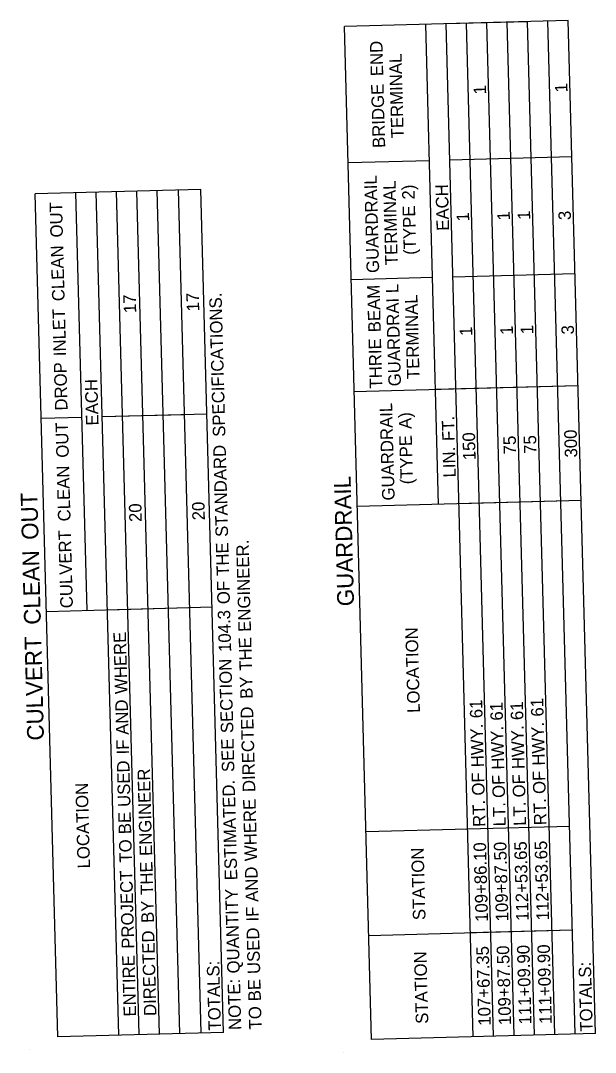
# Model space of a CAD drawing. Extents: x 1930093 to 1931323, y 596452 to 607874.
# Drawn here: x 1930956 to 1931231.4, y 599182.3 to 599676.8 of the extents above; entities that cross this region are included whole.
import ezdxf

# ---------------------------------------------------------------- set-up
doc = ezdxf.new("R2010")
doc.units = 0
doc.layers.add('Default', color=7, linetype='Continuous')
doc.layers.add('R_Border', color=7, linetype='Continuous')

msp = doc.modelspace()

# ---------------------------------------------------------------- linework, layer by layer
at = {"layer": 'Default'}
for p, q in [((1931218.38, 599676.81), (1931111.17, 599673.93)), ((1931198.89, 599676.28), (1931159.9, 599675.24)), ((1931172.93, 599189.86), (1931159.9, 599675.24)), ((1931182.68, 599190.12), (1931169.65, 599675.5)), ((1931192.43, 599190.39), (1931179.4, 599675.76)), ((1931202.17, 599190.65), (1931189.14, 599676.02)), ((1931211.92, 599190.91), (1931198.89, 599676.28)), ((1931221.67, 599191.17), (1931208.64, 599676.55)), ((1931231.41, 599191.43), (1931218.38, 599676.81)), ((1931124.2, 599188.55), (1931111.17, 599673.93)), ((1931156.33, 599444.96), (1931150.16, 599674.98)), ((1931220.14, 599611.51), (1931161.66, 599609.94)), ((1931220.14, 599611.51), (1931161.66, 599609.94)), ((1931151.91, 599609.67), (1931112.92, 599608.63)), ((1931042.44, 599595.93), (1930963, 599593.8)), ((1931042.44, 599595.93), (1930963, 599593.8)), ((1930973.85, 599189.81), (1930963, 599593.8)), ((1930987.87, 599394.03), (1930982.5, 599594.32)), ((1931003.09, 599190.59), (1930992.24, 599594.58)), ((1931012.83, 599190.85), (1931001.99, 599594.84)), ((1931022.58, 599191.11), (1931011.74, 599595.11)), ((1931032.33, 599191.38), (1931021.48, 599595.37)), ((1931042.56, 599191.65), (1931031.72, 599595.64)), ((1931042.56, 599191.65), (1931031.72, 599595.64)), ((1931053.28, 599191.94), (1931042.44, 599595.93)), ((1931153.41, 599553.63), (1931114.43, 599552.59)), ((1931221.64, 599555.46), (1931163.16, 599553.89)), ((1931221.64, 599555.46), (1931163.16, 599553.89)), ((1931223.08, 599501.86), (1931115.87, 599498.98)), ((1931223.08, 599501.86), (1931154.85, 599500.03)), ((1931045.33, 599488.23), (1930995.13, 599486.88)), ((1931034.61, 599487.94), (1930995.13, 599486.88)), ((1930985.39, 599486.62), (1930965.89, 599486.1)), ((1931224.56, 599446.79), (1931117.35, 599443.91)), ((1931224.56, 599446.79), (1931166.08, 599445.22)), ((1931047.81, 599395.64), (1930968.38, 599393.51)), ((1931047.81, 599395.64), (1930997.62, 599394.29)), ((1931219, 599290.58), (1931121.53, 599287.97)), ((1931219, 599290.58), (1931170.26, 599289.28)), ((1931220.33, 599240.88), (1931122.87, 599238.26)), ((1931220.33, 599240.88), (1931171.6, 599239.57)), ((1931053.28, 599191.94), (1930973.85, 599189.81)), ((1931053.28, 599191.94), (1930973.85, 599189.81)), ((1931231.41, 599191.43), (1931124.2, 599188.55)), ((1931231.41, 599191.43), (1931124.2, 599188.55))]:
    msp.add_line(p, q, dxfattribs=at)
at = {"layer": 'R_Border'}
for p, q in [((1930960.36, 599183.59), (1930960.36, 599183.59)), ((1931110.71, 599182.34), (1931110.71, 599182.34))]:
    msp.add_line(p, q, dxfattribs=at)

# ---------------------------------------------------------------- texts
at = {"layer": 'Default'}
for s, height, p in [(' END', 6, (1931129.87, 599648.05)), ('TERMINAL', 6, (1931139.62, 599620.48)), ('BRIDGE', 6, (1931130.74, 599615.87)), ('1', 6, (1931179.12, 599641.52)), ('1', 6, (1931218.1, 599642.47)), ('GUARDRAIL', 6, (1931127.84, 599555.95)), ('TERMINAL', 6, (1931136.75, 599559.69)), (' 2)', 6, (1931144.96, 599588.92)), ('EACH', 6, (1931161.36, 599576.18)), (' OUT', 6, (1930976.38, 599570.73)), ('(TYPE', 6, (1931145.62, 599564.65)), ('1', 6, (1931171, 599580.59)), ('1', 6, (1931190.49, 599581.11)), ('1', 6, (1931200.24, 599581.37)), ('3', 6, (1931219.75, 599581.3)), (' CLEAN', 6, (1930977.2, 599540.2)), (' BEAM', 6, (1931128.67, 599525.31)), ('L', 6, (1931137.11, 599546.26)), ('17', 6, (1931011.43, 599536.74)), ('17', 6, (1931041.64, 599537.54)), (' SPECIFICATIONS.', 6, (1931054.23, 599475.21)), ('GUARDRAI', 6, (1931138.3, 599501.64)), ('TERMINAL', 6, (1931147.21, 599505.11)), (' INLET', 6, (1930977.9, 599513.84)), ('1', 6, (1931172.47, 599525.76)), ('1', 6, (1931191.96, 599526.28)), ('1', 6, (1931201.71, 599526.55)), ('3', 6, (1931221.22, 599526.48)), ('THRIE', 6, (1931129.33, 599500.58)), ('DROP', 6, (1930978.54, 599490.01)), ('EACH', 6, (1930993.37, 599482.83)), ('GUARDRAIL', 6, (1931135.27, 599446.91)), (' A)', 6, (1931143.42, 599478.94)), (' OUT', 6, (1930979.21, 599465.19)), (' FT.', 6, (1931164.13, 599473.19)), ('(TYPE', 6, (1931144.07, 599454.67)), ('150', 6, (1931174.07, 599466.2)), ('75', 6, (1931193.5, 599469.02)), ('75', 6, (1931203.25, 599469.28)), ('300', 6, (1931222.8, 599467.51)), (' STANDARD', 6, (1931055.52, 599427.22)), ('LIN.', 6, (1931164.54, 599457.94)), (' CLEAN', 6, (1930980.03, 599434.66)), ('GUARDRAIL', 8, (1931115.8, 599396.26)), (' OUT', 8, (1930964.7, 599425.12)), ('20', 6, (1931014.11, 599436.6)), ('20', 6, (1931044.33, 599437.42)), ('CULVERT', 6, (1930981.09, 599395.26)), (' THE', 6, (1931056.02, 599408.58)), (' ENGINEER.', 6, (1931066.49, 599381.74)), (' CLEAN', 8, (1930965.8, 599384.42)), (' OF', 6, (1931056.38, 599395)), (' 104.3', 6, (1931057, 599372.09)), (' WHERE', 6, (1931007.31, 599351.94)), ('LOCATION', 6, (1931147.38, 599345.13)), ('CULVERT', 8, (1930967.21, 599331.88)), (' THE', 6, (1931066.99, 599363.1)), (' SECTION', 6, (1931058.04, 599333.2)), (' BY', 6, (1931067.35, 599349.65)), (' AND', 6, (1931007.83, 599332.36)), (' 61', 6, (1931177.45, 599340.31)), (' 61', 6, (1931187.23, 599339.17)), (' 61', 6, (1931196.98, 599339.43)), (' 61', 6, (1931206.69, 599341.09)), (' DIRECTED', 6, (1931068.55, 599304.94)), (' HWY.', 6, (1931178.08, 599316.83)), (' HWY.', 6, (1931207.32, 599317.62)), (' HWY.', 6, (1931187.86, 599315.7)), (' HWY.', 6, (1931197.61, 599315.96)), (' IF', 6, (1931008.09, 599322.97)), (' SEE', 6, (1931058.54, 599314.54)), (' USED', 6, (1931008.76, 599297.81)), (' ENGINEER', 6, (1931019.15, 599274.33)), (' OF', 6, (1931178.44, 599303.25)), (' OF', 6, (1931188.23, 599302.12)), (' OF', 6, (1931197.97, 599302.38)), (' OF', 6, (1931207.68, 599304.03)), ('LOCATION', 6, (1930989.31, 599270.58)), (' ESTIMATED.', 6, (1931059.94, 599262.66)), (' WHERE', 6, (1931069.44, 599271.86)), ('RT.', 6, (1931178.79, 599290.48)), ('LT.', 6, (1931188.53, 599290.74)), ('LT.', 6, (1931198.28, 599291)), ('RT.', 6, (1931208.02, 599291.27)), (' BE', 6, (1931009.11, 599284.75)), (' TO', 6, (1931009.48, 599271.15)), ('STATION', 6, (1931150.05, 599245.79)), ('109+86.10', 6, (1931180.01, 599244.94)), ('109+87.50', 6, (1931189.75, 599245.2)), ('112+53.65', 6, (1931199.5, 599245.43)), ('112+53.65', 6, (1931209.25, 599245.69)), (' THE', 6, (1931019.65, 599255.69)), (' AND', 6, (1931069.97, 599252.29)), (' PROJECT', 6, (1931010.59, 599229.88)), (' QUANTITY', 6, (1931061.13, 599218.02)), (' BY', 6, (1931020.01, 599242.25)), (' IF', 6, (1931070.22, 599242.9)), ('DIRECTED', 6, (1931021.14, 599199.85)), (' USED', 6, (1931070.9, 599217.73)), ('STATION', 6, (1931151.38, 599196.09)), ('107+67.35', 6, (1931181.34, 599195.2)), ('109+87.50', 6, (1931191.09, 599195.49)), ('111+09.90', 6, (1931200.83, 599195.76)), ('111+09.90', 6, (1931210.58, 599196.02)), ('ENTIRE', 6, (1931011.4, 599199.59)), ('TOTALS:', 6, (1931052.06, 599192.88)), ('TOTALS:', 6, (1931230.19, 599192.37)), ('NOTE:', 6, (1931061.8, 599193.14)), (' BE', 6, (1931071.25, 599204.67)), ('TO', 6, (1931071.55, 599193.4))]:
    msp.add_text(s, height=height, rotation=91.5377, dxfattribs=at).set_placement(p)

doc.saveas('drawing.dxf')
